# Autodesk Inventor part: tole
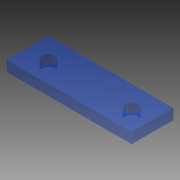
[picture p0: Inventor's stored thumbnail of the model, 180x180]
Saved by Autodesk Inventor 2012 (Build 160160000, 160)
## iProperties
Created: 2013-09
Part Number: tole
Material: Default
Document SubType Name: Modeling
Designer: hilarion
Density: 1 g/cm^3
Author: hilarion
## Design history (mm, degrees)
sketch "Esquisse1"
  geometry: L1 (0, 0)-(40, 0); L2 (40, 0)-(40, 20); L3 (40, 20)-(0, 20); L4 (0, 0)-(-20, 0); L5 (-20, 0)-(-20, 20); L6 (-20, 20)-(0, 20); L7 (40, 20)-(-20, 20); L8 (40, 0)-(-20.264, 0); L9 (-20.264, 0)-(-20, 20); L10 (40, 20)-(40, 0)
  constraints: 20 end point, 3 perpendicular, 2 horizontal, 2 parallel, 1 point on line
  dimensions: "d0" = 40 distance of L3.end L2.end; "d1" = 20 distance of L2.end L1.end; "d11" = 20 distance of L5.end L6.end; "d12" = 20 distance of L4.end L5.end
extrude "Extrusion1" new body sketch "Esquisse1" distance "d2" = 5; taper "d3" = 0 deg
sketch "Esquisse2"
  geometry: 1 further point
hole "Perçage1" sketch "Esquisse2" at (30, 10) diameter "d4" = 6.2; stored, may be unused: countersink angle "d8" = 90 deg, drill point angle "d10" = 118 deg; dims "d5" = 6, "d6" = 4, "d7" = 2, "d9" = 8
sketch "Esquisse4"
  geometry: 2 further points
hole "Perçage2" sketch "Esquisse4" at (-10, 10) diameter "d13" = 6.2; stored, may be unused: countersink angle "d17" = 90 deg, drill point angle "d19" = 118 deg; dims "d14" = 6, "d15" = 4, "d16" = 2, "d18" = 8
node "Solide1"
